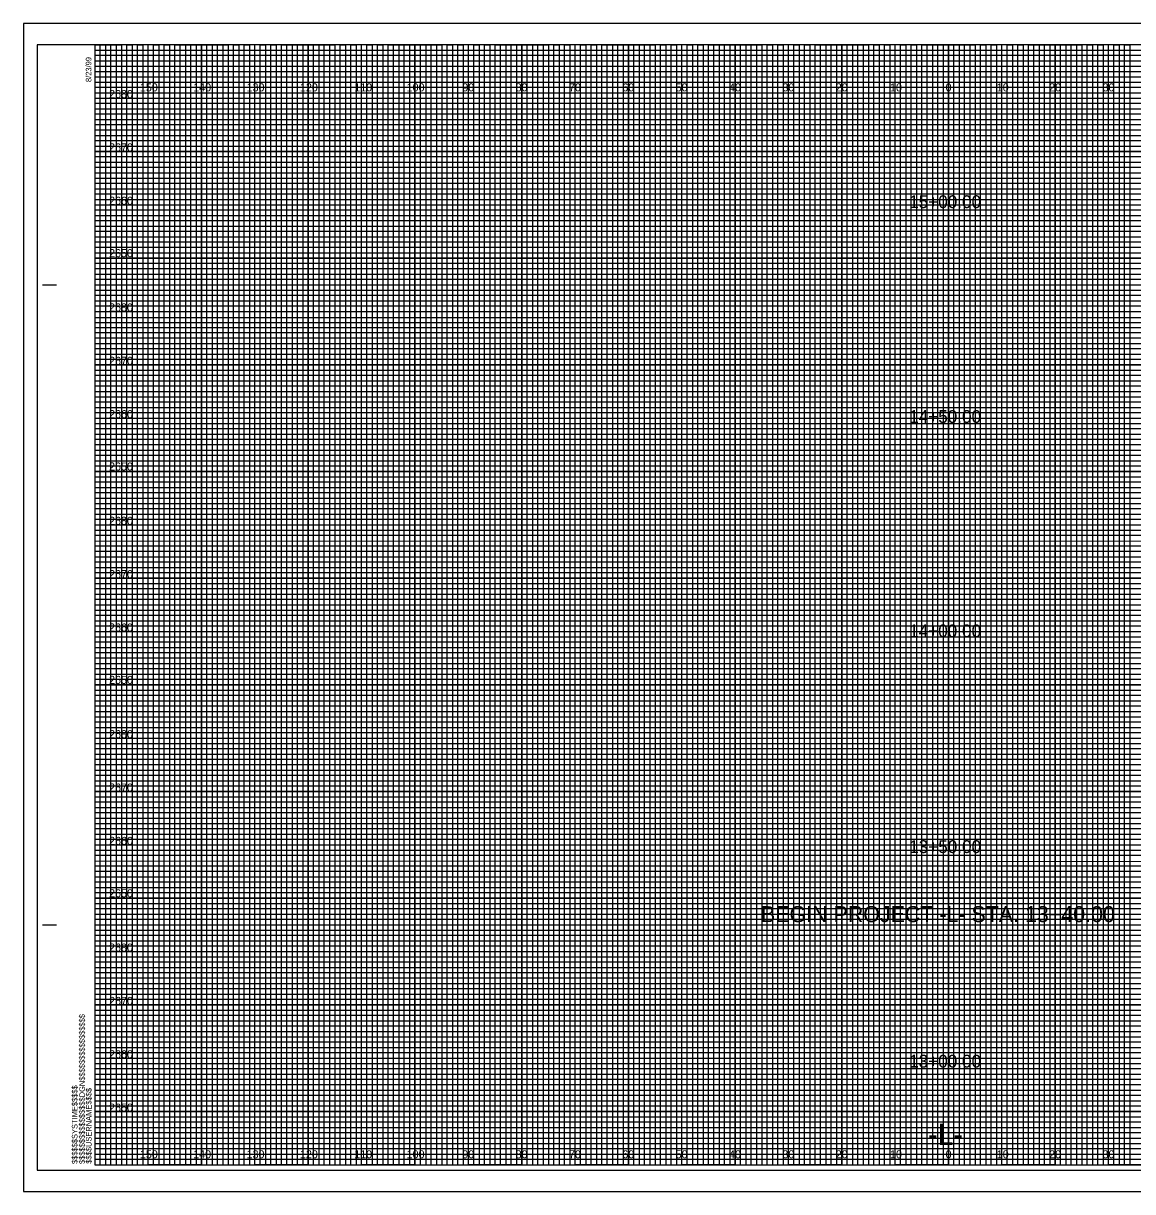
# Model space of a CAD drawing. Extents: x -13 to 371, y -5 to 214.
# Drawn here: x -13.4 to 194.5, y -5 to 214 of the extents above; entities that cross this region are included whole.
import ezdxf

# ---------------------------------------------------------------- set-up
doc = ezdxf.new("R2010")
doc.units = 0
for name, color, linetype in [('Exist Cross Section Cell', 7, 'Continuous'), ('Exist XS Center Line Elevation Label', 7, 'Continuous'), ('Exist XS Ground Line', 7, 'Continuous'), ('Prop XS Ditch Slope Text', 7, 'Continuous'), ('Prop XS Ditch Standard Text', 7, 'Continuous'), ('Prop XS Dump Level', 7, 'Continuous'), ('Prop XS Finish Grade', 7, 'Continuous'), ('Prop XS Finish Grade Earthwork', 7, 'Continuous'), ('Prop XS Finish Grade Pavement', 7, 'Continuous'), ('Prop XS Guardrail', 7, 'Continuous'), ('Prop XS SE Text', 7, 'Continuous'), ('Prop XS Side Slope Text', 7, 'Continuous'), ('Prop XS Subgrade Earthwork', 7, 'Continuous'), ('Prop XS Vertical Lines Alignments', 7, 'Continuous')]:
    doc.layers.add(name, color=color, linetype=linetype)

msp = doc.modelspace()

# ---------------------------------------------------------------- linework, layer by layer
at = {"layer": 'Exist XS Center Line Elevation Label'}
for points in [[(0, 210), (5, 210), (5, 0), (15, 0), (15, 210), (25, 210), (25, 0), (35, 0), (35, 210), (45, 210), (45, 0), (55, 0), (55, 210), (65, 210), (65, 0), (75, 0), (75, 210), (85, 210), (85, 0), (95, 0), (95, 210), (105, 210), (105, 0), (115, 0), (115, 210), (125, 210), (125, 0), (135, 0), (135, 210), (145, 210), (145, 0), (155, 0), (155, 210), (165, 210), (165, 0), (175, 0), (175, 210), (185, 210), (185, 0), (195, 0)], [(0, 205), (275, 205)], [(0, 185), (320, 185), (320, 195), (0, 195)], [(0, 165), (320, 165), (320, 175), (0, 175)], [(0, 145), (320, 145), (320, 155), (0, 155)], [(0, 125), (320, 125), (320, 135), (0, 135)], [(0, 105), (320, 105), (320, 115), (0, 115)], [(0, 85), (320, 85), (320, 95), (0, 95)], [(0, 65), (320, 65), (320, 75), (0, 75)], [(0, 45), (320, 45), (320, 55), (0, 55)], [(0, 25), (320, 25), (320, 35), (0, 35)], [(0, 5), (320, 5), (320, 15), (0, 15)]]:
    msp.add_lwpolyline(points, dxfattribs=at)
at = {"layer": 'Exist XS Ground Line'}
for p, q in [((10, 210), (0, 210)), ((10, 0), (10, 210)), ((30, 210), (20, 210)), ((20, 210), (20, 0)), ((30, 0), (30, 210)), ((50, 210), (40, 210)), ((40, 210), (40, 0)), ((50, 0), (50, 210)), ((70, 210), (60, 210)), ((60, 210), (60, 0)), ((70, 0), (70, 210)), ((90, 210), (80, 210)), ((80, 210), (80, 0)), ((90, 0), (90, 210)), ((110, 210), (100, 210)), ((100, 210), (100, 0)), ((110, 0), (110, 210)), ((130, 210), (120, 210)), ((120, 210), (120, 0)), ((130, 0), (130, 210)), ((150, 210), (140, 210)), ((140, 210), (140, 0)), ((150, 0), (150, 210)), ((170, 210), (160, 210)), ((160, 210), (160, 0)), ((170, 0), (170, 210)), ((190, 210), (180, 210)), ((180, 210), (180, 0)), ((190, 0), (190, 210)), ((20, 0), (10, 0)), ((40, 0), (30, 0)), ((60, 0), (50, 0)), ((80, 0), (70, 0)), ((100, 0), (90, 0)), ((120, 0), (110, 0)), ((140, 0), (130, 0)), ((160, 0), (150, 0)), ((180, 0), (170, 0)), ((200, 0), (190, 0))]:
    msp.add_line(p, q, dxfattribs=at)
for points in [[(0, 200), (320, 200), (320, 190), (0, 190)], [(0, 180), (320, 180), (320, 170), (0, 170)], [(0, 160), (320, 160), (320, 150), (0, 150)], [(0, 140), (320, 140), (320, 130), (0, 130)], [(0, 120), (320, 120), (320, 110), (0, 110)], [(0, 100), (320, 100), (320, 90), (0, 90)], [(0, 80), (320, 80), (320, 70), (0, 70)], [(0, 60), (320, 60), (320, 50), (0, 50)], [(0, 40), (320, 40), (320, 30), (0, 30)], [(0, 20), (320, 20), (320, 10), (0, 10)]]:
    msp.add_lwpolyline(points, dxfattribs=at)
at = {"layer": 'Prop XS Ditch Slope Text'}
msp.add_lwpolyline([(-10.8, -1), (322.4, -1), (322.4, 210), (-10.8, 210)], close=True, dxfattribs=at)
at = {"layer": 'Prop XS Ditch Standard Text'}
msp.add_lwpolyline([(-13.4, -5), (323.3, -5), (323.3, 214), (-13.4, 214)], close=True, dxfattribs=at)
at = {"layer": 'Prop XS Dump Level'}
for p, q in [((0, 209), (260, 209)), ((260, 207.98), (0, 207.98)), ((0, 207.98), (0, 207)), ((0, 207), (260, 207)), ((260, 205.89), (0, 205.89)), ((0, 205.89), (0, 204)), ((0, 204), (320, 204))]:
    msp.add_line(p, q, dxfattribs=at)
for points in [[(0, 203), (270, 203), (320, 203), (320, 202), (0, 202)], [(0, 201), (320, 201), (320, 199), (0, 199)], [(0, 198), (320, 198), (320, 197), (0, 196.98)], [(0, 196), (320, 196), (320, 194), (0, 194)], [(0, 193), (320, 193), (320, 192), (0, 192)], [(0, 191), (320, 191), (320, 189), (0, 189)], [(0, 188), (320, 188), (320, 187), (0, 187)], [(0, 186), (320, 186), (320, 184), (0, 184)], [(0, 183), (320, 183), (320, 182), (0, 182)], [(0, 181), (320, 181), (320, 179), (0, 179)], [(0, 178), (320, 178), (320, 177), (0, 177)], [(0, 176), (320, 176), (320, 173.95), (320, 173), (320, 172), (0, 172)], [(0, 174), (320, 174), (320, 173), (0, 173)], [(0, 171), (320, 171), (320, 169), (0, 169.03)], [(0, 169.03), (320, 169), (320, 168), (0, 168)], [(0, 167), (320, 167), (320, 166), (0, 166)], [(0, 164), (320, 164), (320, 163), (0, 163)], [(0, 162), (320, 162), (320, 161), (0, 161)], [(-0.07, 158.89), (320, 158.89), (320, 157.88), (-0.07, 157.88)], [(0, 157), (320, 157), (320, 156), (0, 156)], [(0, 154), (320, 154), (320, 153), (0, 153)], [(0, 152), (320, 152), (320, 151), (0, 151)], [(0, 149), (320, 149), (320, 148), (0, 148)], [(0, 147), (320, 147), (320, 146), (0, 146)], [(0, 144), (320, 144), (320, 143), (0, 143)], [(0, 142), (320, 142), (320, 141), (0, 141)], [(0, 139), (320, 139), (319.99, 137.98), (0, 138)], [(0, 137), (320, 137), (320, 136), (0, 136)], [(0, 134), (320, 134), (320, 133), (0, 133)], [(0, 132), (320, 132), (320, 131), (0, 131)], [(0, 129), (320, 129), (320, 128), (0, 128)], [(0, 127), (320, 127), (320, 126), (0, 126)], [(0, 124), (320, 124), (320, 123), (0, 123)], [(0, 122), (320, 122), (320, 121), (0, 121)], [(0, 119), (320, 119), (320, 118), (0, 118)], [(0, 116.99), (320.07, 116.91), (320, 116), (0, 116)], [(0, 114), (320, 114), (320, 113), (0, 113)], [(0, 112), (320, 112), (320, 111), (0, 111)], [(0, 109), (320, 109), (320, 108), (0, 108)], [(0, 107), (320, 107), (320, 106), (0, 106)], [(0, 104), (320, 104), (320, 103), (0, 103)], [(0, 102), (320, 102), (320, 101), (0, 101)], [(0, 99), (320, 99), (320, 98), (0, 98)], [(0, 97), (320, 97), (320, 96), (0, 96)], [(0, 94), (320, 94), (320, 93), (0, 93)], [(0, 92), (320, 92), (320, 91), (0, 91)], [(0, 89), (320, 89), (320, 88), (0, 88)], [(0, 87), (320, 87), (320, 86), (0, 86)], [(0, 84), (320, 84), (320, 83), (0, 83)], [(0, 82), (320, 82), (320, 81), (0, 81)], [(0, 79), (320, 79), (319.99, 77.98), (0, 78)], [(0, 77), (320, 77), (320, 76), (0, 76)], [(0, 74), (320, 74), (320, 73), (0, 73)], [(0, 72), (320, 72), (320, 71), (0, 71)], [(0, 69), (320, 69), (320, 68), (0, 68)], [(0, 67), (320, 67), (320, 66), (0, 66)], [(0, 64), (320, 64), (320, 63), (0, 63)], [(0, 62), (320, 62), (320, 61), (0, 61)], [(0, 59), (320, 59), (320, 58), (0, 58)], [(0, 56.99), (320.07, 56.91), (320, 56), (0, 56)], [(0, 54), (320, 54), (320, 53), (0, 53)], [(0, 52), (320, 52), (320, 51), (0, 51)], [(0, 49), (320, 49), (320, 48), (0, 48)], [(0, 47), (320, 47), (320, 46), (0, 46)], [(0, 44), (320, 44), (320, 43), (0, 43)], [(0, 42), (320, 42), (320, 41), (0, 41)], [(0, 39), (320, 39), (320, 38), (0, 38)], [(0, 37), (320, 37), (320, 36), (0, 36)], [(0, 34), (320, 34), (320, 33), (0, 33)], [(0, 32), (320, 32), (320, 31), (0, 31)], [(0, 29), (320, 29), (320, 28), (0, 28)], [(0, 27), (320, 27), (320, 26), (0, 26)], [(0, 24), (320, 24), (320, 23), (0, 23)], [(0, 22), (320, 22), (320, 21), (0, 21)], [(0, 19), (320, 19), (320, 18), (0, 18)], [(0, 17), (320, 17), (320, 16), (0, 16)], [(0, 14), (320, 14), (320, 13), (0, 13)], [(0, 12), (320, 12), (320, 11), (0, 11)], [(0, 9), (320, 9), (320, 8), (0, 8)], [(0, 7), (320, 7), (320, 6), (0, 6)], [(0, 4), (320, 4), (320, 3), (0, 3)], [(0, 2), (320, 2), (320, 1), (0, 1)]]:
    msp.add_lwpolyline(points, dxfattribs=at)
at = {"layer": 'Prop XS Finish Grade Earthwork'}
for p, q in [((10, 0), (10, 210)), ((20, 0), (20, 210)), ((30, 0), (30, 210)), ((40, 0), (40, 210)), ((50, 0), (50, 210)), ((60, 0), (60, 210)), ((70, 0), (70, 210)), ((80, 0), (80, 210)), ((90, 0), (90, 210)), ((100, 0), (100, 210)), ((110, 0), (110, 210)), ((120, 0), (120, 210)), ((130, 0), (130, 210)), ((140, 0), (140, 210)), ((150, 0), (150, 210)), ((160, 0), (160, 210)), ((170, 0), (170, 210)), ((180, 0), (180, 210)), ((190, 0), (190, 210)), ((0, 200), (320, 200)), ((0, 190), (320, 190)), ((0, 180), (320, 180)), ((0, 170), (320, 170)), ((0, 160), (320, 160)), ((0, 150), (320, 150)), ((0, 140), (320, 140)), ((0, 130), (320, 130)), ((0, 120), (320, 120)), ((0, 110), (320, 110)), ((0, 100), (320, 100)), ((0, 90), (320, 90)), ((0, 80), (320, 80)), ((0, 70), (320, 70)), ((0, 60), (320, 60)), ((0, 50), (320, 50)), ((0, 40), (320, 40)), ((0, 30), (320, 30)), ((0, 20), (320, 20)), ((0, 10), (320, 10))]:
    msp.add_line(p, q, dxfattribs=at)
at = {"layer": 'Prop XS SE Text'}
for p, q in [((-9.8, 165), (-7.3, 165)), ((-9.7, 165), (-7.2, 165)), ((-9.8, 45), (-7.3, 45)), ((-9.7, 45), (-7.2, 45)), ((0, 0), (0, 0)), ((0, 0), (0, 0)), ((0, 0), (0, 0)), ((0, 0), (0, 0)), ((0, 0), (0, 0)), ((0, 0), (0, 0)), ((0, 0), (0, 0))]:
    msp.add_line(p, q, dxfattribs=at)
msp.add_lwpolyline([(320, 210), (0, 210), (0, 0), (320, 0)], close=True, dxfattribs=at)
at = {"layer": 'Prop XS Side Slope Text'}
for points in [[(0, 0), (1, 0), (1, 210), (2, 210), (2, 0)], [(2, 0), (3, 0), (3, 210), (4, 210), (4, 0)], [(5, 0), (6, 0), (6, 210), (7, 210), (7, 0)], [(7, 0), (8, 0), (8, 210), (9, 210), (9, 0)], [(10, 0), (11, 0), (11, 210), (12, 210), (12, 0)], [(12, 0), (13, 0), (13, 210), (14, 210), (14, 0)], [(15, 0), (16, 0), (16, 210), (17, 210), (17, 0)], [(17, 0), (18, 0), (18, 210), (19, 210), (19, 0)], [(20, 0), (21, 0), (21, 210), (22, 210), (22, 0)], [(22, 0), (23, 0), (23, 210), (24, 210), (24, 0)], [(25, 0), (26, 0), (26, 210), (27, 210), (27, 0)], [(27, 0), (28, 0), (28, 210), (29, 210), (29, 0)], [(30, 0), (31, 0), (31, 210), (32, 210), (32, 0)], [(32, 0), (33, 0), (33, 210), (34, 210), (34, 0)], [(35, 0), (36, 0), (36, 210), (37, 210), (37, 0)], [(37, 0), (38, 0), (38, 210), (39, 210), (39, 0)], [(40, 0), (41, 0), (41, 210), (42, 210), (42, 0)], [(42, 0), (43, 0), (43, 210), (44, 210), (44, 0)], [(45, 0), (46, 0), (46, 210), (47, 210), (47, 0)], [(47, 0), (48, 0), (48, 210), (49, 210), (49, 0)], [(50, 0), (51, 0), (51, 210), (52, 210), (52, 0)], [(52, 0), (53, 0), (53, 210), (54, 210), (54, 0)], [(55, 0), (56, 0), (56, 210), (57, 210), (57, 0)], [(57, 0), (58, 0), (58, 210), (59, 210), (59, 0)], [(60, 0), (61, 0), (61, 210), (62, 210), (62, 0)], [(62, 0), (63, 0), (63, 210), (64, 210), (64, 0)], [(65, 0), (66, 0), (66, 210), (67, 210), (67, 0)], [(67, 0), (68, 0), (68, 210), (69, 210), (69, 0)], [(70, 0), (71, 0), (71, 210), (72, 210), (72, 0)], [(72, 0), (73, 0), (73, 210), (74, 210), (74, 0)], [(75, 0), (76, 0), (76, 210), (77, 210), (77, 0)], [(77, 0), (78, 0), (78, 210), (79, 210), (79, 0)], [(80, 0), (81, 0), (81, 210), (82, 210), (82, 0)], [(82, 0), (83, 0), (83, 210), (84, 210), (84, 0)], [(85, 0), (86, 0), (86, 210), (87, 210), (87, 0)], [(87, 0), (88, 0), (88, 210), (89, 210), (89, 0)], [(90, 0), (91, 0), (91, 210), (92, 210), (92, 0)], [(92, 0), (93, 0), (93, 210), (94, 210), (94, 0)], [(95, 0), (96, 0), (96, 210), (97, 210), (97, 0)], [(97, 0), (98, 0), (98, 210), (99, 210), (99, 0)], [(100, 0), (101, 0), (101, 210), (102, 210), (102, 0)], [(102, 0), (103, 0), (103, 210), (104, 210), (104, 0)], [(105, 0), (106, 0), (106, 210), (107, 210), (107, 0)], [(107, 0), (108, 0), (108, 210), (109, 210), (109, 0)], [(110, 0), (111, 0), (111, 210), (112, 210), (112, 0)], [(112, 0), (113, 0), (113, 210), (114, 210), (114, 0)], [(115, 0), (116, 0), (116, 210), (117, 210), (117, 0)], [(117, 0), (118, 0), (118, 210), (119, 210), (119, 0)], [(120, 0), (121, 0), (121, 210), (122, 210), (122, 0)], [(122, 0), (123, 0), (123, 210), (124, 210), (124, 0)], [(125, 0), (126, 0), (126, 210), (127, 210), (127, 0)], [(127, 0), (128, 0), (128, 210), (129, 210), (129, 0)], [(130, 0), (131, 0), (131, 210), (132, 210), (132, 0)], [(132, 0), (133, 0), (133, 210), (134, 210), (134, 0)], [(135, 0), (136, 0), (136, 210), (137, 210), (137, 0)], [(137, 0), (138, 0), (138, 210), (139, 210), (139, 0)], [(140, 0), (141, 0), (141, 210), (142, 210), (142, 0)], [(142, 0), (143, 0), (143, 210), (144, 210), (144, 0)], [(145, 0), (146, 0), (146, 210), (147, 210), (147, 0)], [(147, 0), (148, 0), (148, 210), (149, 210), (149, 0)], [(150, 0), (151, 0), (151, 210), (152, 210), (152, 0)], [(152, 0), (153, 0), (153, 210), (154, 210), (154, 0)], [(155, 0), (156, 0), (156, 210), (157, 210), (157, 0)], [(157, 0), (158, 0), (158, 210), (159, 210), (159, 0)], [(160, 0), (161, 0), (161, 210), (162, 210), (162, 0)], [(162, 0), (163, 0), (163, 210), (164, 210), (164, 0)], [(165, 0), (166, 0), (166, 210), (167, 210), (167, 0)], [(167, 0), (168, 0), (168, 210), (169, 210), (169, 0)], [(170, 0), (171, 0), (171, 210), (172, 210), (172, 0)], [(172, 0), (173, 0), (173, 210), (174, 210), (174, 0)], [(175, 0), (176, 0), (176, 210), (177, 210), (177, 0)], [(177, 0), (178, 0), (178, 210), (179, 210), (179, 0)], [(180, 0), (181, 0), (181, 210), (182, 210), (182, 0)], [(182, 0), (183, 0), (183, 210), (184, 210), (184, 0)], [(185, 0), (186, 0), (186, 210), (187, 210), (187, 0)], [(187, 0), (188, 0), (188, 210), (189, 210), (189, 0)], [(190, 0), (191, 0), (191, 210), (192, 210), (192, 0)], [(192, 0), (193, 0), (193, 210), (194, 210), (194, 0)]]:
    msp.add_lwpolyline(points, dxfattribs=at)
at = {"layer": 'Prop XS Subgrade Earthwork'}
for p, q in [((323.3, 214), (-13.4, 214)), ((-13.4, 214), (-13.4, -5)), ((-13.4, -5), (323.3, -5))]:
    msp.add_line(p, q, dxfattribs=at)

# ---------------------------------------------------------------- texts
at = {"layer": 'Exist Cross Section Cell'}
for s, p in [('150', (8.44, 201.25)), ('140', (18.44, 201.25)), ('130', (28.44, 201.25)), ('120', (38.44, 201.25)), ('110', (48.62, 201.25)), ('100', (58.44, 201.25)), ('90', (68.86, 201.25)), ('80', (78.86, 201.25)), ('70', (88.86, 201.25)), ('60', (98.86, 201.25)), ('50', (108.86, 201.25)), ('40', (118.86, 201.25)), ('30', (128.86, 201.25)), ('20', (138.86, 201.25)), ('10', (149.04, 201.25)), ('0', (159.45, 201.25)), ('0', (159.45, 201.25)), ('10', (169.04, 201.25)), ('20', (178.86, 201.25)), ('30', (188.86, 201.25)), ('150', (8.44, 1.25)), ('140', (18.44, 1.25)), ('130', (28.44, 1.25)), ('120', (38.44, 1.25)), ('110', (48.62, 1.25)), ('100', (58.44, 1.25)), ('90', (68.86, 1.25)), ('80', (78.86, 1.25)), ('70', (88.86, 1.25)), ('60', (98.86, 1.25)), ('50', (108.86, 1.25)), ('40', (118.86, 1.25)), ('30', (128.86, 1.25)), ('20', (138.86, 1.25)), ('10', (149.04, 1.25)), ('0', (159.45, 1.25)), ('0', (159.45, 1.25)), ('10', (169.04, 1.25)), ('20', (178.86, 1.25)), ('30', (188.86, 1.25))]:
    msp.add_text(s, height=1.5, dxfattribs=at).set_placement(p)
at = {"layer": 'Prop XS Finish Grade'}
for s, p in [('2680', (2.67, 200)), ('2670', (2.67, 190)), ('2660', (2.67, 180)), ('2650', (2.67, 170.18)), ('2680', (2.67, 160)), ('2670', (2.67, 150)), ('2660', (2.67, 140)), ('2650', (2.67, 130.18)), ('2680', (2.67, 120)), ('2670', (2.67, 110)), ('2660', (2.67, 100)), ('2650', (2.67, 90.18)), ('2680', (2.67, 80)), ('2670', (2.67, 70)), ('2660', (2.67, 60)), ('2650', (2.67, 50.18)), ('2680', (2.67, 40)), ('2670', (2.67, 30)), ('2660', (2.67, 20)), ('2650', (2.67, 10))]:
    msp.add_text(s, height=1.5, dxfattribs=at).set_placement(p)
at = {"layer": 'Prop XS Finish Grade Pavement'}
msp.add_text('-L-', height=4, dxfattribs=at).set_placement((156.15, 3.77))
at = {"layer": 'Prop XS Guardrail'}
for s, p in [('15+00.00', (152.62, 179.37)), ('14+50.00', (152.62, 139.1)), ('14+00.00', (152.62, 98.92)), ('13+50.00', (152.62, 58.47)), ('13+00.00', (152.62, 18.26))]:
    msp.add_text(s, height=2.4, dxfattribs=at).set_placement(p)
at = {"layer": 'Prop XS SE Text'}
for s, p in [('8/23/99', (-0.65, 203)), ('$$$$$$$$$$$$$$$$DGN$$$$$$$$$$$$$$$$', (-1.88, 0.18)), ('$$$$$$SYSTIME$$$$$', (-3.26, 0.18)), ('$$$$USERNAME$$$$', (-0.62, 0.23))]:
    msp.add_text(s, height=1.05, rotation=90, dxfattribs=at).set_placement(p)
at = {"layer": 'Prop XS Vertical Lines Alignments'}
msp.add_text('BEGIN PROJECT -L- STA. 13+40.00', height=3, dxfattribs=at).set_placement((124.84, 45.52))

doc.saveas('drawing.dxf')
